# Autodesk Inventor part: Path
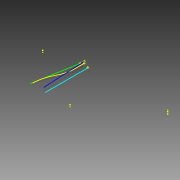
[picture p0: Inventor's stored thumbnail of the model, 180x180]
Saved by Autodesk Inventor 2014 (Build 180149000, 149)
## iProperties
Created: 2009-03
Part Number: Path
Document SubType Name: Modeling
Designer: garding
Density: 1 g/cm^3
Material: Generic
Appearance: Default
Author: garding
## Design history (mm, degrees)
sketch "Paths"
  geometry: L1 (38100, -43.839)-(38100, 20276.161); L2 (41757.6, -43.839)-(45314.16, 20276.161); L3 (39954.2, -43.839)-(38862, 20276.161); L4 (39928.8, -43.839)-(39928.8, 4419.117); A1 r 17780 centre (26259.149, 20349.832) between (41819.631, 11747.519) and (44038.996, 20276.161); A2 r 15146.969 centre (55075.769, 4419.117) between (41819.631, 11747.519) and (39928.8, 4419.117); 1 further point
  constraints: 8 end point, 6 horizontal alignment, 4 point on circle, 2 centre point, 2 tangent, 1 parallel, 1 vertical, 1 other
  dimensions: "d6" = 3657.6 distance of L2.start L1.start; "d10" = 20320 distance of L1.start L1.end; "d13" = 762 distance of L1.end L3.end; "d15" = 1828.8 distance of L1.start L4.start (= 0.5 x d6); "d16" = 1854.2 distance from line of L3.start L1 (computed from d15); "d17" = 17780 radius of A1
workplane "Work Plane1"
workpoint "Work Point1"
workpoint "Work Point2"
sketch "Sketch5"
  geometry: L1 (39954.2, -43.839)-(38862, 20276.161) reference; 1 further point
workpoint "Work Point6"
workplane "Work Plane2"
sketch "Sketch7"
  geometry: L1 (39928.8, -43.839)-(39928.8, 4419.117) reference; A1 r 17780 centre (26259.149, 20349.832) between (41819.631, 11747.519) and (44038.996, 20276.161) reference; A2 r 15146.969 centre (55075.769, 4419.117) between (41819.631, 11747.519) and (39928.8, 4419.117) reference; 1 further point
workpoint "Work Point7"
other parameters: "d7" = 1651, "d14" = 914.4
